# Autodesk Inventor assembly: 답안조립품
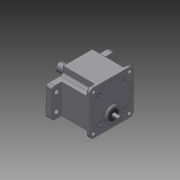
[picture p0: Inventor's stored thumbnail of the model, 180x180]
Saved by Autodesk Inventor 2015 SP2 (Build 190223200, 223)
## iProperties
Created: 2015-06
Part Number: 답안조립품
Document SubType Name: Assembly
Designer: AMC
Author: AMC
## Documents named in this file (12)
- C:\Users\AMC\Desktop\450620V1014\답안조립품.iam
- C:\Users\AMC\Desktop\450620V1014\본체.ipt
- C:\Users\AMC\Desktop\450620V1014\오일실 17x32x8.ipt
- C:\Users\AMC\Desktop\450620V1014\베어링 6003.ipt
- 베어링 6003.ipt
- C:\Users\AMC\Desktop\450620V1014\베어링 608.ipt
- 베어링 608.ipt
- C:\Users\AMC\Desktop\450620V1014\커버.ipt
- C:\Users\AMC\Desktop\450620V1014\오일실 8x22x7.ipt
- C:\Users\AMC\Desktop\450620V1014\M4x0.5x16.ipt
- C:\Users\AMC\Desktop\450620V1014\메인축.ipt
- C:\Users\AMC\Desktop\450620V1014\서브축.ipt
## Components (4 placed, 1 different names)
1. M4x0.5x12:1
2. M4x0.5x12:2
3. M4x0.5x12:3
4. M4x0.5x12:4
